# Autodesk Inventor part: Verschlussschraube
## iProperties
Created: 2006-12
Part Number: Verschlussschraube
Document SubType Name: Modeling
Designer: Kumpf
Manufacturer: Standard
Standards Organization: Custom
Author: Kumpf
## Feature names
1. Drehung1 [Revolution]
2. Fase1 [Chamfer]
3. Fase2 [Chamfer]
4. Fase3 [Chamfer]
